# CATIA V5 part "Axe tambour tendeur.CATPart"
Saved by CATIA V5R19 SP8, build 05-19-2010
Part number: Axe tambour tendeur
Nomenclature: 40a
Material "Acier": density 7860 kg/m3, Young's modulus 2e+11 Pa, Poisson ratio 0.266, thermal expansion 1.17e-05 1/K
Bounding box of the stored display mesh (mm): x -265 to 265, y -7.5 to 7.5, z -7.474 to 7.474
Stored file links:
  C:\Users\rphgr\Desktop\0_Tapis_TC520B_vitesse\Axe tambour tendeur.CATPart
  D:\Programmes\DassaultSysteme\win_b64\reffiles\standard\MetricThickPitch.txt
  D:\Programmes\DassaultSysteme\win_b64\startup\materials\French\Catalog.CATMaterial
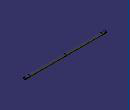
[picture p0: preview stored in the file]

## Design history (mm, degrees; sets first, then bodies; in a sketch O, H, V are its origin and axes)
AxisSystem1: origin (0, 0, 0), X (1, 0, 0), Y (0, 1, 0), Z (0, 0, 1)
Body1 (main body), material "Acier"
  Sketch1 on YZ plane of AxisSystem1, origin (0, 0, 0), H (0, 1, 0), V (0, 0, 1)
    circle A1 centre (0, 0) radius 7.5
    radius A1 = 7.5
  Pad1: profile Sketch1, direction (-1, 0, 0), length 265
  Chamfer1: length 0.5, angle 45, on end face of Pad1
  Sketch2 on ZX plane of AxisSystem1, origin (0, 0, 0), H (0, 0, 1), V (1, 0, 0)
    line L1 (6.75, -236) -> (11.7, -236)
    line L2 (11.7, -236) -> (11.7, -237.1)
    line L3 (11.7, -237.1) -> (6.75, -237.1)
    line L4 (6.75, -237.1) -> (6.75, -236)
    reference projected line E1 through (0, 0) direction (0, 1) from axis of face of Pad1 from Sketch1.A1
    reference intersected line E2 (7.5, -265) -> (-7.5, -265) from end face of Pad1
    distance L4 E1 = 6.75
    distance L1 L3 = 1.1
    distance L1 E2 = 29
    horizontal: L1 H, L3 H
    vertical: L2 V, L4 V
  Groove1: profile Sketch2, axis axis of face of Pad1 from Sketch1.A1, angle 360
  Plane1: type Offset, RefPlane ZX plane of AxisSystem1, Offset 7.5, reversed
  Sketch3 on Plane1, origin (7.7174, -7.5, -10.4756), H (1, 0, 0), V (0, 0, -1)
    point P1 (-264.7174, -10.4756)
    reference intersected point E1 (-272.7174, -10.4756) from end face of Pad1
    reference projected line E2 through (0, -10.4756) direction (1, 0) from axis of face of Pad1 from Sketch1.A1
    distance E1 P1 = 8
    coincidence: P1 E2
  Hole1: placed by Sketch3, at (-257, -7.5, 0) direction (0, -1, 0), diameter 6.647, through (limit type 3), threaded "M8", thread diameter 8, thread depth 0.042, pitch 1.25
  Chamfer2: length 1.5, angle 45, on edge [face of Pad1 from Sketch1.A1 | face of Hole1]
  Mirror1: of the body so far, about start face of Pad1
